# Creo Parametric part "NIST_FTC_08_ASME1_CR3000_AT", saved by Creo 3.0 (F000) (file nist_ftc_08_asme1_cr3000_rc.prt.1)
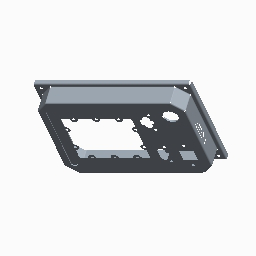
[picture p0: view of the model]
Units: Inch lbm Second (Pro/E Default); INCH, POUND, SECS

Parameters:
  PART_NUMBER = "NIST PMI FTC 08 ASME1"
  REVISION = "C"
  DESCRIPTION = "NIST PMI test model downloaded from http://go.usa.gov/mGVm"

Created from: NIST_FTC_08_ASME1_CR2100_RB_01.PRT

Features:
  1. datum plane "RIGHT"
  2. datum plane "TOP"
  3. datum plane "FRONT"
  4. coordinate system
  5. curve
  6. protrusion
  7. curve
  8. protrusion
  9. pattern
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
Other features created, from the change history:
  datum point "PNT7"
  sketch "Sketch 10"
  extruded cut "Extrude 8"

Other named items: ABC, DBC, DE-F, DG, DHJ, DKL, A, D, B, C, F, E, G, H, J, K, L, AE_GTOL0, AE_GTOL1, AE_SET_DATUM_TAG_A, AE_DRIVEN_DIM0, AE_GTOL2, AE_SET_DATUM_TAG_B, AE_DRIVEN_DIM1, AE_GTOL3, AE_DRIVEN_DIM2, AE_GTOL4, AE_SET_DATUM_TAG_C, AE_GTOL5, AE_GTOL6, AE_SET_DATUM_TAG_D, AE_GTOL7, AE_GTOL8, AE_GTOL9, AE_GTOL10, AE_GTOL11, AE_NOTE1, AE_NOTE2, AE_GTOL12, AE_DRIVEN_DIM3, AE_GTOL13, AE_SET_DATUM_TAG_F, AE_SET_DATUM_TAG_E, AE_GTOL14, AE_GTOL15, AE_GTOL16, AE_GTOL17, AE_GTOL18, AE_GTOL19, AE_DRIVEN_DIM5, AE_GTOL20, AE_SET_DATUM_TAG_G, AE_DRIVEN_DIM6, AE_GTOL21, AE_SET_DATUM_TAG_H, AE_DRIVEN_DIM7, AE_GTOL22, AE_SET_DATUM_TAG_J, AE_DRIVEN_DIM8, AE_GTOL23, AE_SET_DATUM_TAG_K, AE_DRIVEN_DIM9, AE_GTOL24, AE_SET_DATUM_TAG_L, AE_GTOL25, AE_GTOL26, AE_NOTE3, AE_REFERENCE_DIM0, MBD_A, MBD_B, MBD_C, MBD_D, ANNOT_LAYER_STATE0001, ANNOT_LAYER_STATE0002, ANNOT_LAYER_STATE0003, ANNOT_LAYER_STATE0004, LAYER_STATE001, LAYER_STATE002, LAYER_STATE003, LAYER_STATE004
